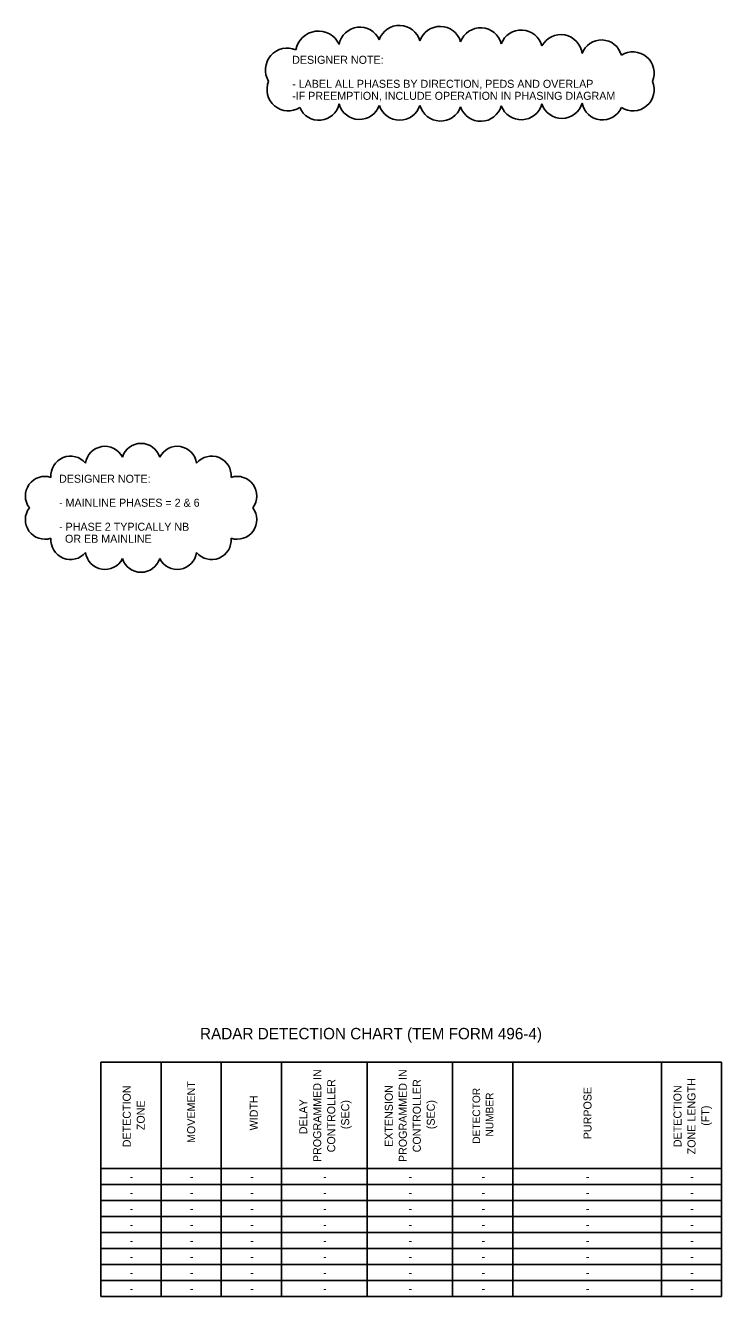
# Model space of a CAD drawing. Extents: x 22.8 to 118.4, y -49.9 to 44.8.
# Drawn here: x 79.51 to 91.7, y 22.6 to 44.84 of the extents above; entities that cross this region are included whole.
import ezdxf

# ---------------------------------------------------------------- set-up
doc = ezdxf.new("R2010")
doc.units = 0
for name, color, linetype in [('SC_Scratch1', 7, 'Continuous'), ('SH_Text', 7, 'Continuous'), ('ST_Text', 7, 'Continuous')]:
    doc.layers.add(name, color=color, linetype=linetype)

msp = doc.modelspace()

# ---------------------------------------------------------------- linework, layer by layer
at = {"layer": 'SC_Scratch1'}
for centre, radius, start, end in [((84.641, 44.338), 0.4, 24.833, 169.833), ((85.369, 44.435), 0.372, 24.0545, 169.0545), ((86.06, 44.464), 0.373, 15.7944, 160.7944), ((86.773, 44.446), 0.374, 16.3895, 161.3895), ((87.482, 44.421), 0.374, 14.4831, 159.4831), ((88.194, 44.384), 0.373, 14.5779, 159.5779), ((88.886, 44.3), 0.376, 6.8087, 151.8087), ((89.598, 44.222), 0.361, 15.0309, 160.0309), ((84.096, 44.058), 0.382, 66.5811, 211.5811), ((90.148, 44), 0.374, 337.5685, 122.5685), ((84.116, 43.715), 0.374, 157.5627, 302.5627), ((90.148, 43.715), 0.374, 237.4315, 22.4315), ((84.651, 43.54), 0.362, 202.6672, 347.6672), ((85.36, 43.561), 0.37, 195.5342, 340.5342), ((86.064, 43.55), 0.372, 197.5, 342.5), ((86.78, 43.537), 0.374, 195.3608, 340.3608), ((87.485, 43.533), 0.374, 199.0296, 344.0296), ((88.195, 43.559), 0.373, 200.0602, 345.0602), ((88.905, 43.579), 0.369, 198.4833, 343.4833), ((89.615, 43.546), 0.362, 191.3271, 336.3271), ((80.904, 37.129), 0.343, 26.8794, 171.8794), ((81.536, 37.181), 0.343, 17.5007, 162.5007), ((82.169, 37.129), 0.343, 8.1222, 153.1222), ((80.301, 36.958), 0.343, 39.8821, 184.8821), ((82.772, 36.958), 0.343, 355.1256, 140.1256), ((79.854, 36.603), 0.343, 72.1184, 217.1184), ((83.219, 36.603), 0.343, 322.8964, 107.8964), ((79.854, 36.189), 0.343, 142.8816, 287.8816), ((83.219, 36.189), 0.343, 252.1036, 37.1036), ((80.301, 35.834), 0.343, 175.1179, 320.1179), ((82.772, 35.834), 0.343, 219.8744, 4.8744), ((80.904, 35.662), 0.343, 188.1206, 333.1206), ((82.169, 35.662), 0.343, 206.8778, 351.8778), ((81.536, 35.611), 0.343, 197.4993, 342.4993)]:
    msp.add_arc(centre, radius, start, end, dxfattribs=at)
at = {"layer": 'ST_Text'}
for p, q in [((80.831, 26.696), (91.702, 26.696)), ((80.831, 26.696), (80.831, 22.595)), ((81.886, 26.696), (81.886, 22.595)), ((82.94, 26.696), (82.94, 22.595)), ((83.994, 26.696), (83.994, 22.595)), ((83.994, 26.696), (83.994, 22.595)), ((85.493, 26.696), (85.493, 22.595)), ((86.991, 26.696), (86.991, 22.595)), ((88.046, 26.696), (88.046, 22.595)), ((90.648, 26.696), (90.648, 22.595)), ((91.702, 26.696), (91.702, 22.595)), ((80.831, 24.836), (91.702, 24.836)), ((80.831, 24.556), (91.702, 24.556)), ((80.831, 24.276), (91.702, 24.276)), ((80.831, 23.996), (91.702, 23.996)), ((80.831, 23.716), (91.702, 23.716)), ((80.831, 23.436), (91.702, 23.436)), ((80.831, 23.156), (91.702, 23.156)), ((80.831, 22.876), (91.702, 22.876)), ((80.831, 22.595), (91.702, 22.595))]:
    msp.add_line(p, q, dxfattribs=at)

# ---------------------------------------------------------------- texts
at = {"layer": 'SC_Scratch1'}
for s, p in [('DESIGNER NOTE:', (84.182, 44.165)), ('- LABEL ALL PHASES BY DIRECTION, PEDS AND OVERLAP', (84.182, 43.745)), ('-IF PREEMPTION, INCLUDE OPERATION IN PHASING DIAGRAM', (84.182, 43.535)), ('DESIGNER NOTE:', (80.101, 36.835)), ('- MAINLINE PHASES = 2 & 6', (80.101, 36.415)), ('- PHASE 2 TYPICALLY NB ', (80.101, 35.995)), ('  OR EB MAINLINE', (80.101, 35.785))]:
    msp.add_text(s, height=0.14, dxfattribs=at).set_placement(p)
at = {"layer": 'SH_Text'}
msp.add_text('RADAR DETECTION CHART (TEM FORM 496-4)', height=0.2, dxfattribs=at).set_placement((82.569, 27.096))
at = {"layer": 'ST_Text'}
for s, height, p in [('PROGRAMMED IN', 0.14, (84.691, 24.949)), ('PROGRAMMED IN', 0.14, (86.19, 24.949)), ('DETECTION', 0.14, (81.356, 25.208)), ('MOVEMENT', 0.14, (82.484, 25.283)), ('CONTROLLER', 0.14, (84.936, 25.119)), ('EXTENSION', 0.14, (85.945, 25.214)), ('CONTROLLER', 0.14, (86.435, 25.119)), ('PURPOSE', 0.14, (89.424, 25.348)), ('DETECTION ', 0.14, (91, 25.21)), ('ZONE LENGTH', 0.14, (91.245, 25.084)), ('WIDTH', 0.14, (83.58, 25.503)), ('DELAY ', 0.14, (84.446, 25.436)), ('DETECTOR', 0.133, (87.474, 25.268)), ('NUMBER', 0.133, (87.706, 25.395)), ('ZONE', 0.14, (81.601, 25.507)), ('(SEC)', 0.14, (85.181, 25.524)), ('(SEC)', 0.14, (86.68, 25.524)), ('(FT)', 0.14, (91.49, 25.584))]:
    msp.add_text(s, height=height, rotation=90, dxfattribs=at).set_placement(p)
for p in [(81.338, 24.625), (82.393, 24.625), (83.447, 24.625), (84.723, 24.625), (86.222, 24.625), (87.499, 24.625), (89.327, 24.625), (91.155, 24.625), (81.338, 24.345), (82.393, 24.345), (83.447, 24.345), (84.723, 24.345), (86.222, 24.345), (87.499, 24.345), (89.327, 24.345), (91.155, 24.345), (81.338, 24.065), (82.393, 24.065), (83.447, 24.065), (84.723, 24.065), (86.222, 24.065), (87.499, 24.065), (89.327, 24.065), (91.155, 24.065), (81.338, 23.785), (82.393, 23.785), (83.447, 23.785), (84.723, 23.785), (86.222, 23.785), (87.499, 23.785), (89.327, 23.785), (91.155, 23.785), (81.338, 23.505), (82.393, 23.505), (83.447, 23.505), (84.723, 23.505), (86.222, 23.505), (87.499, 23.505), (89.327, 23.505), (91.155, 23.505), (81.338, 23.225), (82.393, 23.225), (83.447, 23.225), (84.723, 23.225), (86.222, 23.225), (87.499, 23.225), (89.327, 23.225), (91.155, 23.225), (81.338, 22.945), (82.393, 22.945), (83.447, 22.945), (84.723, 22.945), (86.222, 22.945), (87.499, 22.945), (89.327, 22.945), (91.155, 22.945), (81.338, 22.665), (82.393, 22.665), (83.447, 22.665), (84.723, 22.665), (86.222, 22.665), (87.499, 22.665), (89.327, 22.665), (91.155, 22.665)]:
    msp.add_text('-', height=0.14, dxfattribs=at).set_placement(p)

doc.saveas('drawing.dxf')
